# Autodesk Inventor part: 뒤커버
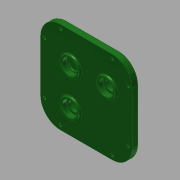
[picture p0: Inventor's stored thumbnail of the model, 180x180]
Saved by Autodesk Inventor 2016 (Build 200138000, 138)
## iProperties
Created: 2016-12
Part Number: 뒤커버
Material: 일반
Document SubType Name: Modeling
Designer: mduedu
Density: 1 g/cm^3
Appearance: 매끄러움 - 짙은 산림 녹색
Mass: 179.104 g
Surface Area: 454.562 cm^2
Volume: 179.104 cm^3
Author: mduedu
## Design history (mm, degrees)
sketch "스케치1"
  geometry: L1 (-46, 42)-(-46, -36); L2 (-16, 72)-(62, 72); L3 (92, 42)-(92, -36); L4 (62, -66)-(-16, -66); A1 r 30 centre (-16, -36) between (-46, -36) and (-16, -66); A2 r 30 centre (62, 42) between (92, 42) and (62, 72); A3 r 30 centre (62, -36) between (62, -66) and (92, -36); A4 r 30 centre (-16, 42) between (-16, 72) and (-46, 42); 1 further point
  constraints: 8 end point, 8 point on circle, 8 tangent, 4 centre point, 3 equal radius, 2 perpendicular, 1 horizontal, 1 vertical
  dimensions: "d80" = 30 radius of A2; "d81" = 138 distance between parallel lines of L4 L2; "d82" = 92 distance from line of L3 point (0, 0); "d114" = 46 distance from line of L1 point (0, 0); "d115" = 72 distance from line of L2 point (0, 0)
extrude "돌출1" new body sketch "스케치1" distance "d3" = 10; taper "d4" = 0 deg
sketch "스케치2"
  geometry: C1 r 14 at (0, 26); 1 further point
  constraints: 1 centre point, 1 vertical alignment
  dimensions: "d5" = 28 diameter of C1; "d6" = 26 distance of C1.centre point (0, 0)
extrude "돌출2" join sketch "스케치2" distance "d7" = 3; taper "d8" = 0 deg
sketch "스케치3"
  geometry: C1 r 14 at (0, -28.87); C2 r 14 at (0, 26) reference; C3 r 14 at (54.87, 26); 1 further point
  constraints: 2 centre point, 1 horizontal alignment, 1 vertical alignment
  dimensions: "d9" = 28 diameter of C1; "d69" = 54.87 distance of C1.centre C2.centre; "d83" = 28 diameter of C3; "d84" = 54.87 distance of C3.centre C2.centre
extrude "돌출3" join sketch "스케치3" distance "d11" = 3; taper "d12" = 0 deg
hole "구멍1" diameter "d15" = 22; stored, may be unused: countersink angle "d19" = 90 deg, drill point angle "d21" = 0 deg; dims "d13" = 10, "d14" = 10, "d16" = 6, "d17" = 4, "d18" = 2, "d20" = 7
hole "구멍2" diameter "d24" = 18; stored, may be unused: countersink angle "d28" = 90 deg, drill point angle "d30" = 0 deg; dims "d22" = 10, "d23" = 10, "d25" = 6, "d26" = 4, "d27" = 2, "d29" = 1
hole "구멍3" diameter "d33" = 22; stored, may be unused: countersink angle "d37" = 90 deg, drill point angle "d39" = 0 deg; dims "d31" = 10, "d32" = 10, "d34" = 6, "d35" = 4, "d36" = 2, "d38" = 7
hole "구멍7" diameter "d87" = 22; stored, may be unused: countersink angle "d91" = 90 deg, drill point angle "d93" = 0 deg; dims "d85" = 10, "d86" = 10, "d88" = 6, "d89" = 4, "d90" = 2, "d92" = 7
sketch "스케치4"
  geometry: C1 r 14 at (0, -28.87) reference; C2 r 18 at (0, -28.87); C3 r 14 at (-54.87, 26) reference; C4 r 18 at (-54.87, 26); 1 further point
  constraints: 2 centre point, 2 coincident
  dimensions: "d40" = 36 diameter of C2; "d94" = 36 diameter of C4
extrude "돌출4" join sketch "스케치4" distance "d41" = 4; taper "d42" = 0 deg
hole "구멍4" diameter "d45" = 22; stored, may be unused: countersink angle "d49" = 90 deg, drill point angle "d51" = 0 deg; dims "d43" = 10, "d44" = 10, "d46" = 6, "d47" = 4, "d48" = 2, "d50" = 7
hole "구멍8" diameter "d97" = 22; stored, may be unused: countersink angle "d101" = 90 deg, drill point angle "d103" = 0 deg; dims "d95" = 10, "d96" = 10, "d98" = 6, "d99" = 4, "d100" = 2, "d102" = 7
hole "구멍5" diameter "d54" = 15; stored, may be unused: countersink angle "d58" = 90 deg, drill point angle "d60" = 0 deg; dims "d52" = 10, "d53" = 10, "d55" = 6, "d56" = 4, "d57" = 2, "d59" = 7
hole "구멍9" diameter "d106" = 15; stored, may be unused: countersink angle "d110" = 90 deg, drill point angle "d112" = 0 deg; dims "d104" = 10, "d105" = 10, "d107" = 6, "d108" = 4, "d109" = 2, "d111" = 7
fillet "모깎기1" dims "d61" = 0.3
fillet "모깎기2" dims "d62" = 2
chamfer "모따기1" distance "d63" = 1; stored, may be unused: second distance "d64" = 2, angle "d65" = 45 deg
fillet "모깎기3" dims "d66" = 2
fillet "모깎기4" dims "d67" = 2
fillet "모깎기5" dims "d68" = 2
sketch "스케치5"
  geometry: L1 (-62, 72)-(16, 72) reference; L2 (-92, -36)-(-92, 42) reference; L3 (16, -66)-(-62, -66) reference; L4 (46, 42)-(46, -36) reference; L5 (16, 66)-(-62, 66); L6 (-86, 42)-(-86, -36); L7 (-62, -60)-(16, -60); L8 (40, -36)-(40, 42); A1 r 30 centre (-62, 42) between (-62, 72) and (-92, 42) reference; A2 r 30 centre (-62, -36) between (-92, -36) and (-62, -66) reference; A3 r 30 centre (16, -36) between (16, -66) and (46, -36) reference; A4 r 30 centre (16, 42) between (46, 42) and (16, 72) reference; A5 r 24 centre (-62, 42) between (-62, 66) and (-86, 42); A6 r 24 centre (-62, -36) between (-86, -36) and (-62, -60); A7 r 24 centre (16, -36) between (16, -60) and (40, -36); A8 r 24 centre (16, 42) between (40, 42) and (16, 66)
  constraints: 8 end point, 8 point on circle, 4 centre point, 7 other
  dimensions: "d113" = 6 distance between parallel lines of L6 L2
sketch "스케치6"
  geometry: L1 (16, 66)-(-62, 66) reference; L2 (40, -36)-(40, 42) reference; L3 (-62, -60)-(16, -60) reference; L4 (-86, 42)-(-86, -36) reference; A1 r 24 centre (16, 42) between (40, 42) and (16, 66) reference; A2 r 24 centre (16, -36) between (16, -60) and (40, -36) reference; A3 r 24 centre (-62, -36) between (-86, -36) and (-62, -60) reference; A4 r 24 centre (-62, 42) between (-62, 66) and (-86, 42) reference; 8 further points
  constraints: 8 coincident
hole "구멍6" sketch "스케치6" at (-62, 66), (-86, 42), (-86, -36), (-62, -60), (16, -60), (40, -36), (40, 42), (16, 66) diameter "d71" = 4.5; stored, may be unused: countersink angle "d75" = 90 deg, drill point angle "d77" = 0 deg; dims "d72" = 6, "d73" = 8, "d74" = 4.6, "d76" = 8
node "솔리드1"
